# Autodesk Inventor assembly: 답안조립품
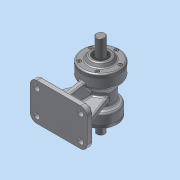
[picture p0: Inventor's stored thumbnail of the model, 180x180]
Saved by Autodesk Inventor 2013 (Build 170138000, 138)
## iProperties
Created: 2015-08
Part Number: 답안조립품
Document SubType Name: Assembly
Designer: Administrator
Author: Administrator
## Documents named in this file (10)
- C:\Users\Administrator\Desktop\450806V1012\답안조립품.iam
- C:\Users\Administrator\Desktop\450806V1012\본체.ipt
- C:\Users\Administrator\Desktop\450806V1012\M4x0.5.ipt
- C:\Users\Administrator\Desktop\450806V1012\뒤커버.ipt
- C:\Users\Administrator\Desktop\450806V1012\베어링 6203.ipt
- C:\Users\Administrator\Desktop\450806V1012\베어링 6205.ipt
- C:\Users\Administrator\Desktop\450806V1012\앞커버.ipt
- C:\Users\Administrator\Desktop\450806V1012\오일실 .ipt
- 오일실 .ipt
- C:\Users\Administrator\Desktop\450806V1012\축.ipt
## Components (10 placed, 1 different names)
1. M4x0.5:2
2. M4x0.5:3
3. M4x0.5:4
4. M4x0.5:5
5. M4x0.5:6
6. M4x0.5:1
7. M4x0.5:7
8. M4x0.5:8
9. M4x0.5:9
10. M4x0.5:10
